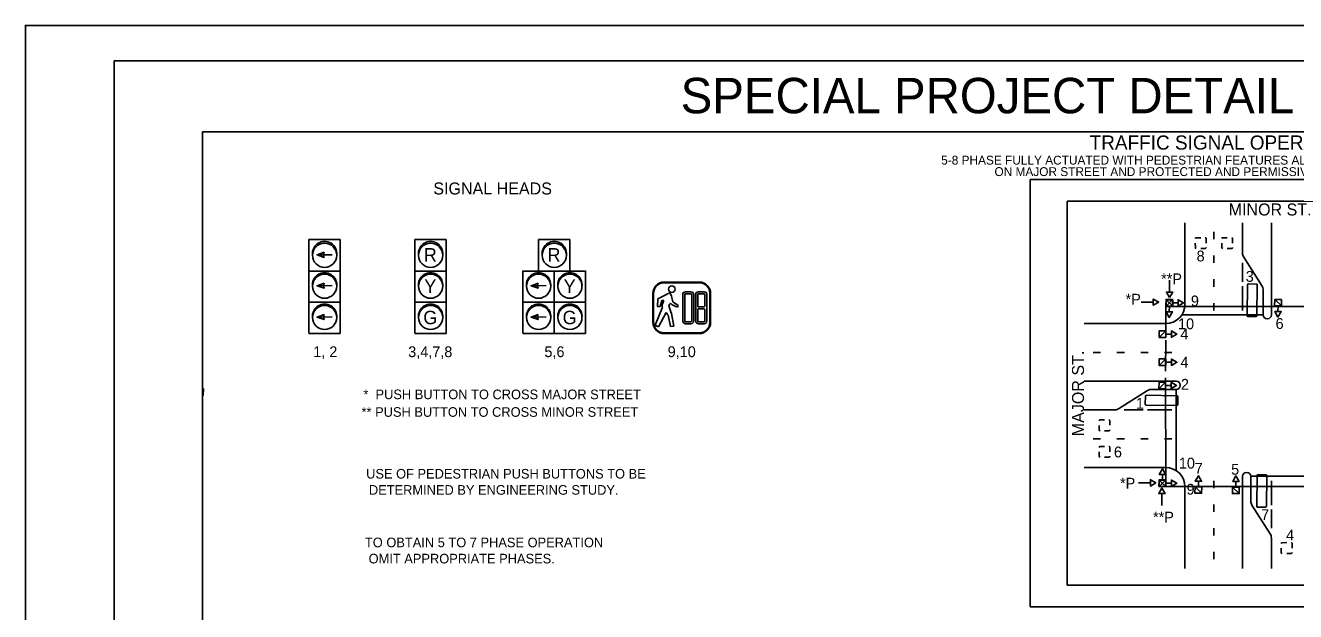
# Model space of a CAD drawing. Extents: x 515543 to 517243, y 660510 to 662861.
# Drawn here: x 515543 to 516438, y 661197 to 661610 of the extents above; entities that cross this region are included whole.
import ezdxf

# ---------------------------------------------------------------- set-up
doc = ezdxf.new("R2010")
doc.units = 0
for name, color, linetype in [('1', 7, 'Continuous'), ('2', 7, 'Continuous'), ('ANNO-SHT', 7, 'Continuous'), ('Default', 7, 'Continuous'), ('DRAINAGE', 7, 'Continuous'), ('Level 1', 7, 'Continuous'), ('Level 62', 7, 'Continuous'), ('RED', 7, 'Continuous'), ('SHT-BDR', 7, 'Continuous'), ('SHT-BNDRY', 7, 'Continuous'), ('Signal Design', 7, 'Continuous'), ('TEXT', 7, 'Continuous'), ('WIRING PLAN', 7, 'Continuous'), ('YELLOW', 7, 'Continuous')]:
    doc.layers.add(name, color=color, linetype=linetype)

# ---------------------------------------------------------------- blocks, each defined once
blk = doc.blocks.new('SC47208')
at = {"layer": 'Level 1'}
blk.add_line((0, 0), (0, 0), dxfattribs=at)
blk = doc.blocks.new('A$C10762150_1')
at = {"layer": 'Signal Design'}
for p, q in [((-0.33, -0.36), (0.33, 0.36)), ((-0.33, -0.36), (0.33, 0.36)), ((-0.94, -0.02), (-0.35, -0.01))]:
    blk.add_line(p, q, dxfattribs=at)
for points in [[(-0.93, -0.36), (-0.95, 0.31), (-1.52, -0.04)], [(0.35, -0.35), (-0.33, -0.36), (-0.35, 0.35), (0.33, 0.36)]]:
    blk.add_lwpolyline(points, close=True, dxfattribs=at)
for points in [[(-1.52, -0.04), (-0.93, -0.36), (-0.95, 0.31), (-1.52, -0.04)], [(-0.33, -0.36), (0.35, -0.35), (0.33, 0.36), (-0.35, 0.35), (-0.33, -0.36)]]:
    blk.add_lwpolyline(points, dxfattribs=at)
blk = doc.blocks.new('A$C57205C4C_1')
at = {"layer": 'Signal Design'}
blk.add_blockref('A$C10762150_1', (0, 0), dxfattribs=at)

msp = doc.modelspace()

# ---------------------------------------------------------------- linework, layer by layer
at = {"layer": '1'}
for p, q in [((515742.51, 661459.17), (515764.59, 661459.17)), ((515742.51, 661437.08), (515742.51, 661459.17)), ((515764.59, 661459.17), (515764.59, 661437.08)), ((515817.26, 661459.17), (515839.35, 661459.17)), ((515817.26, 661437.08), (515817.26, 661459.17)), ((515839.35, 661459.17), (515839.35, 661437.08)), ((515904.47, 661459.17), (515926.56, 661459.17)), ((515904.47, 661437.08), (515904.47, 661459.17)), ((515926.56, 661459.17), (515926.56, 661437.08)), ((515742.51, 661393.22), (515742.51, 661437.08)), ((515742.51, 661436.98), (515764.59, 661436.98)), ((515764.59, 661437.08), (515764.59, 661392.91)), ((515817.26, 661393.22), (515817.26, 661437.08)), ((515817.26, 661436.98), (515839.35, 661436.98)), ((515839.35, 661437.08), (515839.35, 661392.91)), ((515893.43, 661393.22), (515893.43, 661437.08)), ((515893.43, 661436.98), (515915.52, 661436.98)), ((515915.52, 661437.08), (515915.52, 661392.91)), ((515915.52, 661393.22), (515915.52, 661437.08)), ((515915.52, 661436.98), (515937.6, 661436.98)), ((515937.6, 661437.08), (515937.6, 661392.91)), ((515742.51, 661414.99), (515764.59, 661414.99)), ((515817.26, 661414.99), (515839.35, 661414.99)), ((515893.43, 661414.99), (515915.52, 661414.99)), ((515915.52, 661414.99), (515937.6, 661414.99)), ((515764.59, 661392.91), (515742.51, 661392.91)), ((515839.35, 661392.91), (515817.26, 661392.91)), ((515915.52, 661392.91), (515893.43, 661392.91)), ((515937.6, 661392.91), (515915.52, 661392.91))]:
    msp.add_line(p, q, dxfattribs=at)
for centre in [(515753.55, 661448.12), (515828.3, 661448.12), (515915.52, 661448.12), (515753.55, 661426.35), (515828.3, 661426.35), (515904.47, 661426.35), (515926.56, 661426.35), (515753.55, 661404.27), (515828.3, 661404.27), (515904.47, 661404.27), (515926.56, 661404.27)]:
    msp.add_circle(centre, 8.52, dxfattribs=at)
for centre, radius, start, end in [((515753.55, 661449.34), 8.57, 353.97442, 186.02558), ((515828.3, 661449.34), 8.57, 353.97442, 186.02558), ((515915.52, 661449.34), 8.57, 353.97442, 186.02558), ((515753.55, 661427.22), 8.6, 352.10963, 187.89037), ((515828.3, 661427.22), 8.6, 352.10963, 187.89037), ((515904.47, 661427.22), 8.6, 352.10963, 187.89037), ((515926.56, 661427.22), 8.6, 352.10963, 187.89037), ((515753.55, 661405.17), 8.57, 353.97442, 186.02558), ((515828.3, 661405.17), 8.57, 353.97442, 186.02558), ((515904.47, 661405.17), 8.57, 353.97442, 186.02558), ((515926.56, 661405.17), 8.57, 353.97442, 186.02558)]:
    msp.add_arc(centre, radius, start, end, dxfattribs=at)
at = {"layer": '2'}
msp.add_lwpolyline([(515668.07, 661354.17), (515668, 661349.17)], dxfattribs=at)
msp.add_lwpolyline([(515668.07, 661354.17), (515668, 661349.17)], dxfattribs=at)
at = {"layer": 'Default'}
for p, q in [((516251.21, 661200.31), (516251.21, 661501.62)), ((516251.21, 661501.62), (516574.21, 661501.62)), ((516277.29, 661486.39), (516548.12, 661486.39)), ((516277.29, 661486.39), (516277.29, 661215.55)), ((516371.46, 661460.53), (516368.29, 661460.52)), ((516375.28, 661456.74), (516375.27, 661459.91)), ((516380.68, 661459.43), (516380.68, 661464.66)), ((516390.15, 661460.53), (516386.97, 661460.52)), ((516393.97, 661456.74), (516393.96, 661459.91)), ((515748.21, 661448.36), (515753.15, 661450.24)), ((515758.78, 661448.52), (515748.21, 661448.36)), ((515748.21, 661448.36), (515753.2, 661446.62)), ((515753.15, 661450.24), (515752.65, 661448.43)), ((515752.65, 661448.43), (515753.2, 661446.62)), ((516367.67, 661456.71), (516367.68, 661453.54)), ((516374.66, 661452.93), (516371.49, 661452.92)), ((516380.68, 661442.7), (516380.68, 661447.93)), ((516386.35, 661456.71), (516386.36, 661453.54)), ((516393.34, 661452.93), (516390.17, 661452.92)), ((516400.99, 661429.51), (516400.99, 661442.74)), ((516349.52, 661422.15), (516349.52, 661430.61)), ((516380.68, 661425.97), (516380.68, 661431.2)), ((515748.21, 661426.59), (515753.15, 661428.47)), ((515758.78, 661426.75), (515748.21, 661426.59)), ((515748.21, 661426.59), (515753.2, 661424.85)), ((515753.15, 661428.47), (515752.65, 661426.65)), ((515752.65, 661426.65), (515753.2, 661424.85)), ((515899.13, 661426.59), (515904.07, 661428.47)), ((515909.71, 661426.75), (515899.13, 661426.59)), ((515899.13, 661426.59), (515904.13, 661424.85)), ((515904.07, 661428.47), (515903.57, 661426.65)), ((515903.57, 661426.65), (515904.13, 661424.85)), ((516400.99, 661409.24), (516400.99, 661426.46)), ((516337.99, 661415.06), (516329.53, 661415.06)), ((516346.77, 661402.74), (516346.82, 661413.51)), ((516478.88, 661412.02), (516346.82, 661412.02)), ((516380.68, 661409.24), (516380.68, 661414.47)), ((515748.21, 661404.5), (515753.15, 661406.39)), ((515758.78, 661404.66), (515748.21, 661404.5)), ((515748.21, 661404.5), (515753.2, 661402.77)), ((515753.15, 661406.39), (515752.65, 661404.57)), ((515752.65, 661404.57), (515753.2, 661402.77)), ((515899.13, 661404.5), (515904.07, 661406.39)), ((515909.71, 661404.66), (515899.13, 661404.5)), ((515899.13, 661404.5), (515904.13, 661402.77)), ((515904.07, 661406.39), (515903.57, 661404.57)), ((515903.57, 661404.57), (515904.13, 661402.77)), ((516346.77, 661402.74), (516346.81, 661392.86)), ((516346.77, 661388.16), (516346.61, 661366.38)), ((516300.9, 661379.66), (516295.67, 661379.66)), ((516317.63, 661379.66), (516312.4, 661379.66)), ((516334.36, 661379.66), (516329.13, 661379.66)), ((516351.1, 661379.66), (516345.87, 661379.66)), ((516346.56, 661361.68), (516346.8, 661289.74)), ((516303.6, 661332.01), (516300.42, 661332)), ((516307.42, 661328.21), (516307.41, 661331.39)), ((516330.83, 661339.03), (516317.59, 661339.03)), ((516351.1, 661339.03), (516333.88, 661339.03)), ((516299.8, 661328.19), (516299.81, 661325.01)), ((516306.79, 661324.4), (516303.62, 661324.39)), ((516300.9, 661318.72), (516295.67, 661318.72)), ((516317.63, 661318.72), (516312.4, 661318.72)), ((516334.36, 661318.72), (516329.13, 661318.72)), ((516351.1, 661318.72), (516345.87, 661318.72)), ((516299.8, 661309.5), (516299.81, 661306.33)), ((516303.6, 661313.32), (516300.42, 661313.31)), ((516306.79, 661305.72), (516303.62, 661305.71)), ((516307.42, 661309.53), (516307.41, 661312.7)), ((516336.07, 661287.56), (516327.6, 661287.56)), ((516380.68, 661289.14), (516380.68, 661283.91)), ((516421.3, 661289.14), (516421.3, 661271.92)), ((516344.11, 661280.06), (516344.11, 661271.6)), ((516346.76, 661285.04), (516478.97, 661285.04)), ((516380.68, 661272.41), (516380.68, 661267.18)), ((516421.3, 661268.87), (516421.3, 661255.63)), ((516380.68, 661255.67), (516380.68, 661250.44)), ((516432.12, 661245.46), (516428.95, 661245.45)), ((516435.94, 661241.66), (516435.93, 661244.84)), ((516380.68, 661238.94), (516380.68, 661233.71)), ((516428.32, 661241.64), (516428.33, 661238.46)), ((516435.32, 661237.85), (516432.15, 661237.84)), ((516277.29, 661215.55), (516548.12, 661215.55)), ((516251.21, 661200.31), (516574.21, 661200.31))]:
    msp.add_line(p, q, dxfattribs=at)
for points in [[(516360.36, 661413.51), (516360.36, 661471.06)], [(516400.99, 661449.66), (516400.99, 661471.06)], [(516421.3, 661406.06), (516421.3, 661471.06)], [(515753.15, 661450.24), (515748.21, 661448.36), (515753.2, 661446.62), (515752.65, 661448.43), (515753.15, 661450.24)], [(516414.7, 661426.46), (516401.83, 661446.76)], [(515753.15, 661428.47), (515748.21, 661426.59), (515753.2, 661424.85), (515752.65, 661426.65), (515753.15, 661428.47)], [(515904.07, 661428.47), (515899.13, 661426.59), (515904.13, 661424.85), (515903.57, 661426.65), (515904.07, 661428.47)], [(516349.55, 661418.3), (516351.73, 661422.17), (516347.3, 661422.13), (516349.55, 661418.3)], [(516404.5, 661427.36), (516404.18, 661405.65)], [(516410.79, 661427.84), (516405.08, 661427.92)], [(516411.04, 661405.55), (516411.35, 661427.26)], [(516415.55, 661406.06), (516415.55, 661423.56)], [(516341.84, 661415.09), (516337.97, 661417.28), (516338.01, 661412.84), (516341.84, 661415.09)], [(515753.15, 661406.39), (515748.21, 661404.5), (515753.2, 661402.77), (515752.65, 661404.57), (515753.15, 661406.39)], [(515904.07, 661406.39), (515899.13, 661404.5), (515904.13, 661402.77), (515903.57, 661404.57), (515904.07, 661406.39)], [(516415.55, 661406.06), (516358.13, 661406.06)], [(516404.75, 661405.07), (516410.46, 661404.99)], [(516418.59, 661403.35), (516418.25, 661403.35)], [(516346.82, 661399.97), (516289.27, 661399.97)], [(516354.27, 661359.34), (516289.27, 661359.34)], [(516333.88, 661352.75), (516313.57, 661339.87)], [(516354.78, 661349.08), (516333.08, 661349.4)], [(516354.27, 661353.59), (516336.78, 661353.59)], [(516354.27, 661353.59), (516354.27, 661296.17)], [(516356.98, 661356.64), (516356.98, 661356.3)], [(516332.5, 661348.83), (516332.41, 661343.12)], [(516332.98, 661342.54), (516354.68, 661342.23)], [(516355.26, 661342.79), (516355.34, 661348.5)], [(516310.67, 661339.03), (516289.27, 661339.03)], [(516346.82, 661298.41), (516289.27, 661298.41)], [(516339.92, 661287.59), (516336.05, 661289.78), (516336.09, 661285.34), (516339.92, 661287.59)], [(516400.99, 661292.31), (516400.99, 661227.31)], [(516403.7, 661295.02), (516404.04, 661295.02)], [(516406.74, 661292.31), (516462.55, 661292.31)], [(516406.74, 661292.31), (516406.74, 661274.82)], [(516411.25, 661292.82), (516410.94, 661271.12)], [(516417.54, 661293.3), (516411.83, 661293.39)], [(516417.79, 661271.02), (516418.11, 661292.72)], [(516344.07, 661283.91), (516341.89, 661280.04), (516346.32, 661280.08), (516344.07, 661283.91)], [(516360.36, 661284.86), (516360.36, 661227.31)], [(516407.59, 661271.92), (516420.46, 661251.61)], [(516411.5, 661270.54), (516417.21, 661270.45)], [(516421.3, 661248.71), (516421.3, 661227.31)]]:
    msp.add_lwpolyline(points, dxfattribs=at)
for centre, radius, start, end in [((516368.29, 661459.89), 0.635, 90.18841, 180.18841), ((516374.64, 661459.91), 0.635, 0.18841, 90.18841), ((516386.97, 661459.89), 0.635, 90.18841, 180.18841), ((516393.32, 661459.91), 0.635, 0.18841, 90.18841), ((516368.31, 661453.54), 0.635, 180.18841, 270.18841), ((516374.66, 661453.56), 0.635, 270.18841, 0.18841), ((516386.99, 661453.54), 0.635, 180.18841, 270.18841), ((516393.34, 661453.56), 0.635, 270.18841, 0.18841), ((516406.41, 661449.66), 5.42, 180, 212.37247), ((516405.07, 661427.35), 0.571, 89.16504, 179.16504), ((516410.78, 661427.27), 0.571, 359.16504, 89.16504), ((516410.13, 661423.56), 5.42, 360, 32.37247), ((516346.82, 661413.51), 13.54, 270, 0), ((516404.76, 661405.64), 0.571, 179.16504, 269.16504), ((516410.47, 661405.56), 0.571, 269.16504, 359.16504), ((516418.25, 661406.06), 2.71, 180, 270), ((516418.59, 661406.06), 2.71, 270, 0), ((516354.27, 661356.64), 2.71, 0, 90), ((516333.07, 661348.83), 0.571, 89.16504, 179.16504), ((516336.78, 661348.17), 5.42, 90, 122.37247), ((516354.27, 661356.3), 2.71, 270, 0), ((516332.98, 661343.11), 0.571, 179.16504, 269.16504), ((516354.69, 661342.8), 0.571, 269.16504, 359.16504), ((516354.77, 661348.51), 0.571, 359.16504, 89.16504), ((516300.42, 661331.36), 0.635, 90.18841, 180.18841), ((516306.77, 661331.38), 0.635, 0.18841, 90.18841), ((516310.67, 661344.45), 5.42, 270, 302.37247), ((516300.44, 661325.02), 0.635, 180.18841, 270.18841), ((516306.79, 661325.04), 0.635, 270.18841, 0.18841), ((516300.42, 661312.68), 0.635, 90.18841, 180.18841), ((516300.44, 661306.33), 0.635, 180.18841, 270.18841), ((516306.77, 661312.7), 0.635, 0.18841, 90.18841), ((516306.79, 661306.35), 0.635, 270.18841, 0.18841), ((516346.82, 661284.86), 13.54, 0, 90), ((516403.7, 661292.31), 2.71, 90, 180), ((516404.04, 661292.31), 2.71, 0, 90), ((516411.82, 661292.82), 0.571, 89.16504, 179.16504), ((516417.54, 661292.73), 0.571, 359.16504, 89.16504), ((516412.16, 661274.82), 5.42, 180, 212.37247), ((516411.51, 661271.11), 0.571, 179.16504, 269.16504), ((516417.22, 661271.03), 0.571, 269.16504, 359.16504), ((516415.89, 661248.71), 5.42, 0, 32.37247), ((516428.95, 661244.81), 0.635, 90.18841, 180.18841), ((516435.3, 661244.83), 0.635, 0.18841, 90.18841), ((516428.97, 661238.47), 0.635, 180.18841, 270.18841), ((516435.32, 661238.49), 0.635, 270.18841, 0.18841)]:
    msp.add_arc(centre, radius, start, end, dxfattribs=at)
at = {"layer": 'Level 62'}
msp.add_lwpolyline([(515542.51, 660510.25), (517242.52, 660510.25), (517242.52, 661610.25), (515542.51, 661610.25)], close=True, dxfattribs=at)
at = {"layer": 'RED'}
for p, q in [((515993.08, 661429.26), (516017.69, 661429.26)), ((515993.08, 661429), (516017.69, 661429)), ((515993.08, 661428.75), (516017.69, 661428.75)), ((516025.26, 661421.18), (516025.26, 661400.99)), ((516025.51, 661421.18), (516025.51, 661400.99)), ((516025.76, 661421.18), (516025.76, 661400.99)), ((516023.15, 661420.38), (516023.15, 661401.79)), ((516021.74, 661409.81), (516021.74, 661401.79)), ((516017.69, 661393.41), (515993.08, 661393.41)), ((516017.69, 661393.16), (515993.08, 661393.16)), ((516017.69, 661392.91), (515993.08, 661392.91))]:
    msp.add_line(p, q, dxfattribs=at)
for centre, radius, start, end in [((515993.08, 661421.18), 8.08, 90, 180), ((515993.08, 661421.18), 7.82, 90, 180), ((515993.08, 661421.18), 7.57, 90, 180), ((516017.69, 661421.18), 8.08, 0, 90), ((516017.69, 661421.18), 7.82, 0, 90), ((516017.69, 661421.18), 7.57, 0, 90), ((515993.08, 661400.99), 8.08, 180, 270), ((515993.08, 661400.99), 7.82, 180, 270), ((515993.08, 661400.99), 7.57, 180, 270), ((516017.69, 661400.99), 8.08, 270, 0), ((516017.69, 661400.99), 7.82, 270, 0), ((516017.69, 661400.99), 7.57, 270, 0)]:
    msp.add_arc(centre, radius, start, end, dxfattribs=at)
at = {"layer": 'SHT-BDR'}
msp.add_lwpolyline([(515667.5, 660585.3), (517167.5, 660585.3), (517167.5, 661535.3), (515667.5, 661535.3)], close=True, dxfattribs=at)
at = {"layer": 'SHT-BNDRY'}
msp.add_lwpolyline([(515605.01, 660535.25), (517217.52, 660535.25), (517217.52, 661585.25), (515605.01, 661585.25)], close=True, dxfattribs=at)
at = {"layer": 'Signal Design'}
for points in [[(516349.55, 661418.3), (516349.55, 661418.3), (516351.73, 661422.17), (516347.3, 661422.13)], [(516341.84, 661415.09), (516341.84, 661415.09), (516337.97, 661417.28), (516338.01, 661412.84)], [(516339.92, 661287.59), (516339.92, 661287.59), (516336.05, 661289.78), (516336.09, 661285.34)], [(516344.07, 661283.91), (516344.07, 661283.91), (516341.89, 661280.04), (516346.32, 661280.08)]]:
    msp.add_lwpolyline(points, close=True, dxfattribs=at)
at = {"layer": 'TEXT'}
for p, q in [((515992.82, 661419.45), (515995.79, 661421.17)), ((515995.79, 661421.17), (515996.43, 661421.54)), ((515996.43, 661421.54), (515996.99, 661421.32)), ((515996.99, 661421.32), (515997.54, 661420.67)), ((515988.67, 661417.36), (515988.38, 661411.9)), ((515990.16, 661412.08), (515988.38, 661411.9)), ((515988.67, 661417.36), (515989.48, 661417.93)), ((515989.48, 661417.93), (515992.82, 661419.45)), ((515991.35, 661416.27), (515990.16, 661412.08)), ((515992.77, 661416.27), (515991.35, 661416.27)), ((515991.53, 661412.9), (515991.58, 661413.18)), ((515991.54, 661412.52), (515991.53, 661412.9)), ((515991.55, 661412.17), (515991.54, 661412.52)), ((515991.64, 661411.87), (515991.55, 661412.17)), ((515991.58, 661413.18), (515992.77, 661416.27)), ((515996.89, 661413.44), (515996.39, 661412.25)), ((515996.39, 661412.25), (515996.74, 661410.99)), ((515997.31, 661413.98), (515996.89, 661413.44)), ((515997.58, 661414.33), (515997.31, 661413.98)), ((515997.54, 661420.67), (515998.15, 661419.62)), ((515998.67, 661413.24), (515997.58, 661414.33)), ((515998.15, 661419.62), (515998.5, 661418.09)), ((515998.5, 661418.09), (515999.07, 661415.38)), ((516002.45, 661411.6), (515998.67, 661413.24)), ((515999.07, 661415.38), (516003.02, 661412.71)), ((516003.02, 661412.71), (516002.45, 661411.6)), ((515986.75, 661398.94), (515991.85, 661411.49)), ((515994.42, 661407.75), (515988.94, 661397.57)), ((515991.85, 661411.49), (515991.64, 661411.87)), ((515994.85, 661407.17), (515994.42, 661407.75)), ((515995.44, 661406.41), (515994.85, 661407.17)), ((515995.94, 661405.8), (515995.44, 661406.41)), ((515997.61, 661397.8), (515995.94, 661405.8)), ((515996.74, 661410.99), (515997.84, 661408.25)), ((515997.84, 661408.25), (515998.25, 661406.98)), ((515998.25, 661406.98), (515999.84, 661398.08)), ((515988.94, 661397.57), (515986.75, 661398.94)), ((515999.84, 661398.08), (515997.61, 661397.8))]:
    msp.add_line(p, q, dxfattribs=at)
msp.add_circle((515998.51, 661424.29), 2.33, dxfattribs=at)
at = {"layer": 'WIRING PLAN'}
for p, q in [((516008.06, 661422.35), (516011.94, 661422.35)), ((516008.06, 661420.94), (516011.94, 661420.94)), ((516017.29, 661422.35), (516021.18, 661422.35)), ((516017.29, 661420.94), (516021.18, 661420.94)), ((516006.09, 661420.38), (516006.09, 661401.79)), ((516007.5, 661420.38), (516007.5, 661401.79)), ((516012.51, 661420.38), (516012.51, 661401.79)), ((516013.91, 661420.38), (516013.91, 661401.79)), ((516015.32, 661420.38), (516015.32, 661401.79)), ((516016.73, 661420.38), (516016.73, 661412.35)), ((516021.74, 661420.38), (516021.74, 661412.35)), ((516016.73, 661409.81), (516016.73, 661401.79)), ((516017.29, 661411.79), (516021.18, 661411.79)), ((516017.29, 661410.38), (516021.18, 661410.38)), ((516008.06, 661401.23), (516011.94, 661401.23)), ((516008.06, 661399.82), (516011.94, 661399.82)), ((516017.29, 661401.23), (516021.18, 661401.23)), ((516017.29, 661399.82), (516021.18, 661399.82))]:
    msp.add_line(p, q, dxfattribs=at)
for centre, radius, start, end in [((516008.06, 661420.38), 1.97, 90, 180), ((516008.06, 661420.38), 0.563, 90, 180), ((516011.94, 661420.38), 1.97, 0, 90), ((516011.94, 661420.38), 0.563, 0, 90), ((516017.29, 661420.38), 1.97, 90, 180), ((516017.29, 661420.38), 0.563, 90, 180), ((516021.18, 661420.38), 1.97, 0, 90), ((516021.18, 661420.38), 0.563, 0, 90), ((516017.29, 661412.35), 0.563, 180, 270), ((516021.18, 661412.35), 0.563, 270, 0), ((516017.29, 661409.81), 0.563, 90, 180), ((516021.18, 661409.81), 0.563, 0, 90), ((516008.06, 661401.79), 1.97, 180, 270), ((516008.06, 661401.79), 0.563, 180, 270), ((516011.94, 661401.79), 1.97, 270, 0), ((516011.94, 661401.79), 0.563, 270, 0), ((516017.29, 661401.79), 1.97, 180, 270), ((516017.29, 661401.79), 0.563, 180, 270), ((516021.18, 661401.79), 1.97, 270, 0), ((516021.18, 661401.79), 0.563, 270, 0)]:
    msp.add_arc(centre, radius, start, end, dxfattribs=at)
at = {"layer": 'YELLOW'}
for p, q in [((515985, 661400.99), (515985, 661421.18)), ((515985.25, 661400.99), (515985.25, 661421.18)), ((515985.51, 661400.99), (515985.51, 661421.18))]:
    msp.add_line(p, q, dxfattribs=at)

# ---------------------------------------------------------------- block references
at = {"layer": 'DRAINAGE', "xscale": 1.0000020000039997, "yscale": 1.0000020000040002, "rotation": -116.41666666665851}
msp.add_blockref('SC47208', (516419.1, 661561.24), dxfattribs=at)
msp.add_blockref('SC47208', (516419.1, 661561.24), dxfattribs=at)
at = {"layer": 'Signal Design', "xscale": 6.664206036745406, "yscale": 6.664206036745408}
for p, rotation in [((516349.37, 661414.47), 88.26073256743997), ((516349.29, 661414.55), 178.26073256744), ((516426.01, 661414.66), 88.26073256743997), ((516344.52, 661392.56), 178.26073256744), ((516344.52, 661372.72), 178.26073256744), ((516344.32, 661356.36), 178.26073256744), ((516344.42, 661287.33), -91.73926743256), ((516344.51, 661287.41), 178.26073256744), ((516369.8, 661282.56), -91.73926743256), ((516396.29, 661282.36), -91.73926743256)]:
    msp.add_blockref('A$C57205C4C_1', p, dxfattribs=dict(at, rotation=rotation))

# ---------------------------------------------------------------- texts
at = {"layer": '1'}
for s, p in [('R', (515823.53, 661443.71)), ('R', (515910.74, 661443.71)), ('Y', (515823.89, 661421.62)), ('Y', (515922.15, 661421.62)), ('G', (515823.16, 661399.53)), ('G', (515921.42, 661399.53))]:
    msp.add_text(s, height=9.47, dxfattribs=at).set_placement(p)
at = {"layer": 'ANNO-SHT'}
msp.add_text('         SPECIAL PROJECT DETAIL         ', height=24.9975, dxfattribs=at).set_placement((515921.08, 661548.26))
at = {"layer": 'Default'}
for s, height, p in [('TRAFFIC SIGNAL OPERATING PLAN', 10, (516293.14, 661522.64)), ("5-8 PHASE FULLY ACTUATED WITH PEDESTRIAN FEATURES ALL PHASE'S WITH PROTECTED LEFT TURN'S", 6.25, (516188.42, 661512.09)), ('ON MAJOR STREET AND PROTECTED AND PERMISSIVE LEFT TURNS ON MINOR STREET', 6.25, (516226.01, 661504)), ('SIGNAL HEADS', 8.4635, (515830.23, 661491.01)), ('MINOR ST.', 8.464, (516391.18, 661476.2)), ('*P', 7.617, (516318.5, 661413.34)), ('1, 2', 7.617, (515745.54, 661376.3)), ('3,4,7,8', 7.617, (515812.5, 661376.3)), ('5,6', 7.617, (515908.58, 661376.3)), ('9,10', 7.617, (515995.51, 661376.3)), ('*  PUSH BUTTON TO CROSS MAJOR STREET ', 6.7708, (515780.9, 661346.65)), ('** PUSH BUTTON TO CROSS MINOR STREET ', 6.7708, (515779.61, 661334.23)), ('        USE OF PEDESTRIAN PUSH BUTTONS TO BE', 6.7708, (515762.71, 661290.67)), ('7', 7.62, (516367.26, 661294.12)), ('5', 7.62, (516392.95, 661293.37)), ('*P', 7.617, (516314.56, 661283.59)), ('9', 7.62, (516361.46, 661279.32)), ('DETERMINED BY ENGINEERING STUDY.', 6.7708, (515784.79, 661279.27)), ('7', 7.62, (516414.11, 661261.46)), ('**P', 7.617, (516337.86, 661259.65)), ('4', 7.62, (516431.7, 661247.01)), ('              TO OBTAIN 5 TO 7 PHASE OPERATION ', 6.7708, (515746.78, 661242.23)), ('OMIT APPROPRIATE PHASES.', 6.7708, (515784.6, 661230.82))]:
    msp.add_text(s, height=height, dxfattribs=at).set_placement(p)
for s, height, rotation, p in [('8', 7.62, 360, (516368.56, 661443.8)), ('**P', 7.617, 360, (516343.55, 661427.73)), ('3', 7.62, 360, (516403.22, 661429.4)), ('9', 7.62, 360, (516364.53, 661412.12)), ('10', 7.617, 360, (516355.47, 661395.97)), ('6', 7.62, 360, (516424.3, 661396.2)), ('4', 7.62, 360, (516357.2, 661388.83)), ('MAJOR ST.', 8.464, 90, (516289.16, 661320.51)), ('4', 7.62, 360, (516357.2, 661368.99)), ('2', 7.62, 360, (516357.54, 661353.34)), ('1', 7.62, 360, (516325.77, 661339.93)), ('6', 7.62, 360, (516310.26, 661305.59)), ('10', 7.617, 360, (516356.07, 661297.73))]:
    msp.add_text(s, height=height, rotation=rotation, dxfattribs=at).set_placement(p)

doc.saveas('drawing.dxf')
